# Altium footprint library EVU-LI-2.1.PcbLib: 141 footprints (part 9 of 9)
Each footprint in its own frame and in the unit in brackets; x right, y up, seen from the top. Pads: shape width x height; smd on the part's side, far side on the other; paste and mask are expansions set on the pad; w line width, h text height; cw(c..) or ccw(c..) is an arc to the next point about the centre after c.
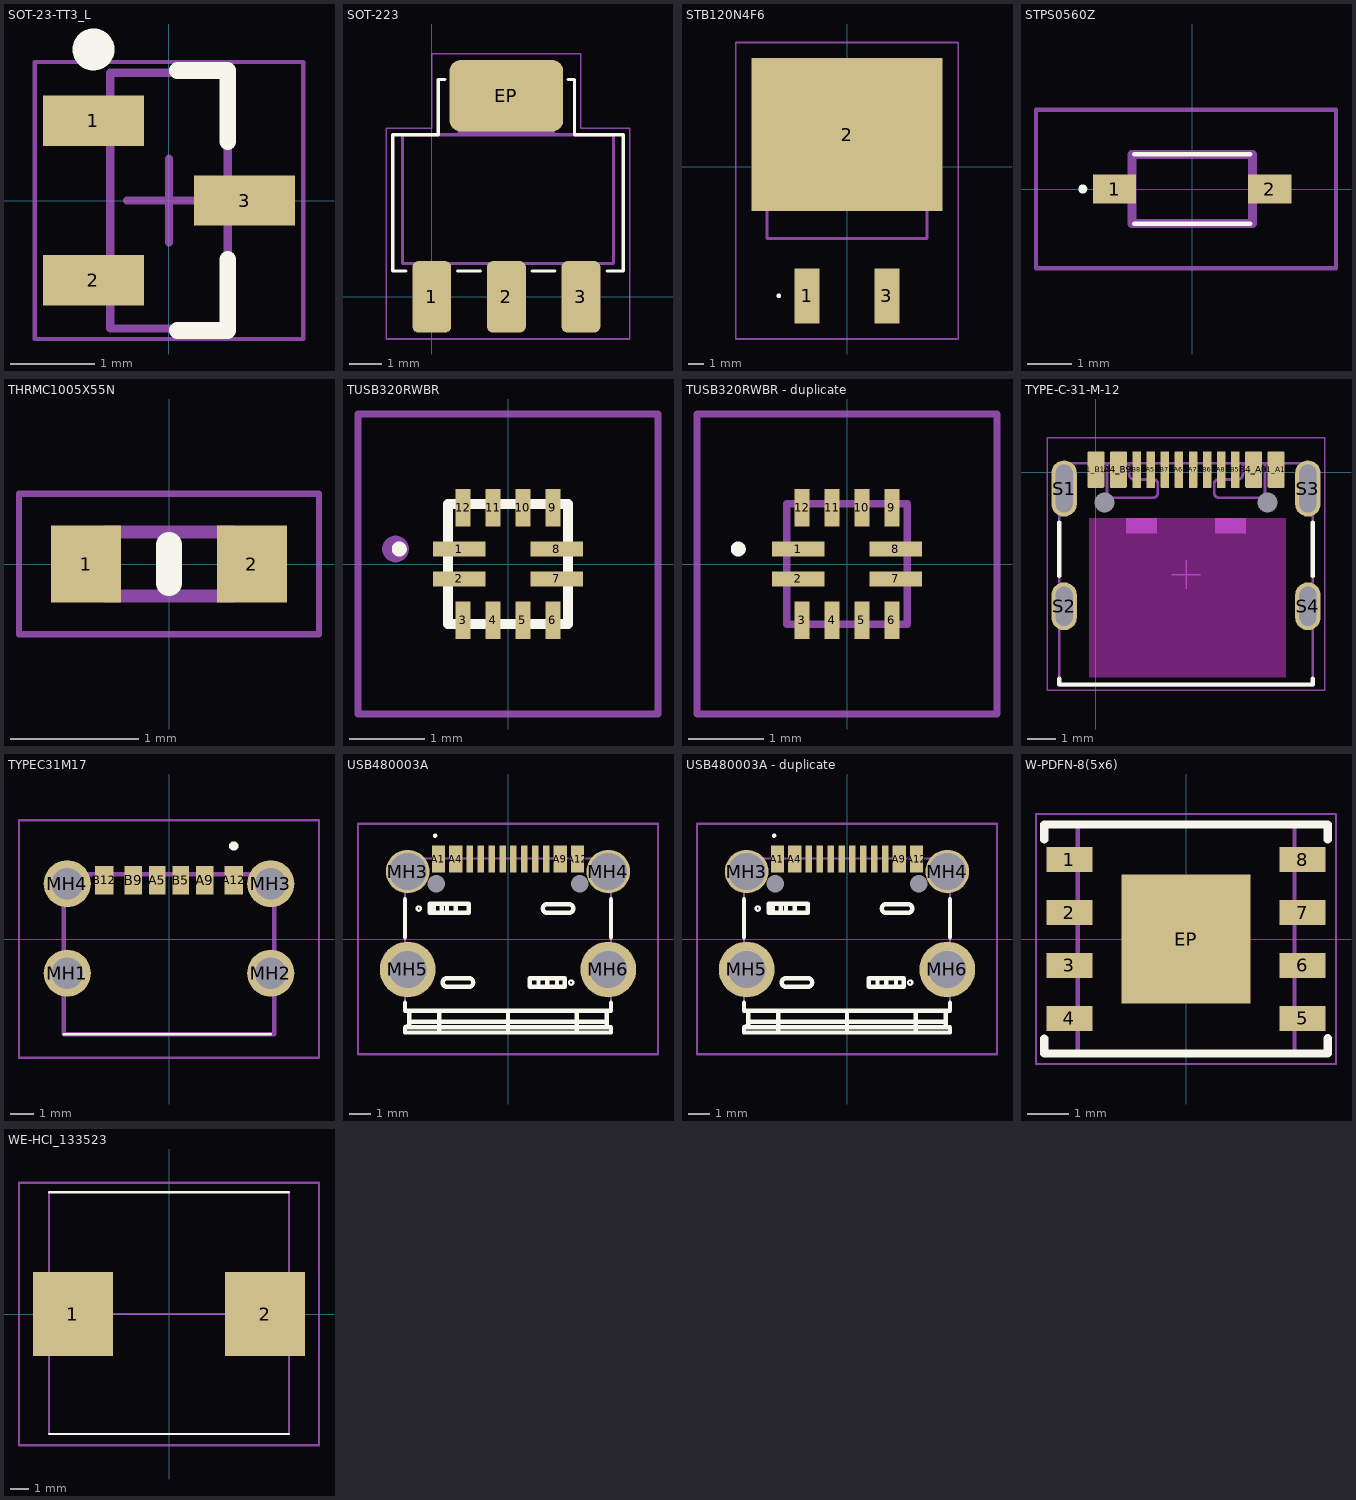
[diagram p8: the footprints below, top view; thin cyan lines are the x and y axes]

## SOT-23-TT3_L [mm] "SOT23, 3-Leads, Body 2.9x1.3mm, Pitch 0.95mm, Lead Span 2.4mm, IPC High Density"
height 1.12
pads (3):
  rect 1.2x0.6 smd: 1(-0.9,0.95) 2(-0.9,-0.95) 3(0.9,0)
Top Overlay:
  circle w0.25: c-0.9,1.8 r0.125
  lines w0.2: 0.1,-1.55 0.7,-1.55 0.7,-0.7 ; 0.1,1.55 0.7,1.55 0.7,0.7
Mechanical 13:
  lines w0.1: -0.7,-1.525 -0.7,1.525 0.7,1.525 0.7,-1.525 -0.7,-1.525
Top Courtyard:
  lines w0.05: -1.6,-1.65 -1.6,1.65 1.6,1.65 1.6,-1.65 -1.6,-1.65
  lines w0.1: -0.5,0 0.5,0 ; 0,-0.5 0,0.5
3D body: height 1.12, standoff 0.01, extent -0.7,-1.525 0.7,1.525

## SOT-223 [mm]
height 1.1
pads (4):
  rrect30% 1.2x2.2 smd mask+0.05: 1(0,0) 2(2.3,0) 3(4.6,0)
  rrect30% 3.5x2.2 smd mask+0.05: EP(2.3,6.2)
Top Overlay:
  lines w0.1: -0.8,0.8 -1.2,0.8 -1.2,5 0.2,5 0.2,6.7 0.4,6.7 ; 0.8,0.8 1.5,0.8 ; 3.1,0.8 3.8,0.8 ; 4.2,6.7 4.4,6.7 4.4,5 5.9,5 5.9,0.8 5.4,0.8
  text "." at -1.1,-0.3 h5
Top Assembly:
  rectangle: 4.2,-0.42 5,1
  rectangle: 1.9,-0.42 2.7,1
  region: 3.8,6.6 0.8,6.6 0.8,5 3.8,5
  rectangle: -0.4,-0.42 0.4,1
  lines w0.1: -0.9,1.03 -0.9,5 5.6,5 5.6,1.03 -0.9,1.03
  text ".Designator" at 0.604,3.246 h0.8
  text "." at -0.1,1.3 h3
Top Value:
  text ".Comment" at 1.251,2.771 h0.5
Top Courtyard:
  lines w0.05: -1.4,-1.3 6.1,-1.3 6.1,5.199 4.599,5.199 4.599,7.5 0.001,7.5 0.001,5.199 -1.4,5.199 -1.4,-1.3
3D body "SOT223-3.step": height 1.6, standoff 0, extent -0.9,-0.437 5.6,6.637

## STB120N4F6 [mm]
pads (3):
  rect 1.6x3.5 smd: 1(-2.54,-8.24) 3(2.54,-8.24)
  rect 12.2x9.75 smd: 2(0,2.035)
Top Overlay:
  lines w0.2: -4.4,-8.24 ccw(c-4.35,-8.24) -4.3,-8.24 ; -4.4,-8.24 cw(c-4.35,-8.24) -4.3,-8.24 ; -4.4,-8.24 ccw(c-4.35,-8.24) -4.3,-8.24
Mechanical 13:
  lines w0.2: -5.1,-4.575 -5.1,4.575 5.1,4.575 5.1,-4.575 -5.1,-4.575
Top Courtyard:
  lines w0.1: -7.1,-10.99 -7.1,7.91 7.1,7.91 7.1,-10.99 -7.1,-10.99
3D body "STB140NF75T4.stp": height 4.6, standoff -0.05, extent -5.194,-8.103 5.194,5.375

## STPS0560Z [mm]
pads (2):
  rect 0.97x0.65 smd: 1(-1.74,0) 2(1.74,0)
Top Overlay:
  lines w0.1: -1.3,-0.775 1.3,-0.775 ; -1.3,0.775 1.3,0.775 ; -2.5,0 ccw(c-2.45,0) -2.4,0 ccw(c-2.45,0) -2.5,0
Mechanical 13:
  lines w0.2: -1.35,-0.775 1.35,-0.775 1.35,0.775 -1.35,0.775 -1.35,-0.775
Top Courtyard:
  lines w0.1: -3.5,-1.775 3.225,-1.775 3.225,1.775 -3.5,1.775 -3.5,-1.775
3D body "STPS0560Z.stp": height 1.45, standoff 0, extent -1.975,-0.85 1.975,0.85

## THRMC1005X55N [mm]
pads (2):
  rect 0.55x0.6 smd: 1(-0.65,0) 2(0.65,0)
Top Overlay:
  lines w0.2: 0,-0.15 0,0.15
Mechanical 13:
  lines w0.1: -0.5,-0.25 0.5,-0.25 0.5,0.25 -0.5,0.25 -0.5,-0.25
Top Courtyard:
  lines w0.05: -1.175,-0.55 1.175,-0.55 1.175,0.55 -1.175,0.55 -1.175,-0.55
3D body "NTCG103JF103F.stp": height 0.55, standoff 0, extent -0.5,-0.25 0.5,0.25

## TUSB320RWBR [mm]
pads (12):
  rect 0.7x0.2 smd: 1(-0.65,0.2) 2(-0.65,-0.2) 7(0.65,-0.2) 8(0.65,0.2)
  rect 0.2x0.5 smd: 3(-0.6,-0.75) 4(-0.2,-0.75) 5(0.2,-0.75) 6(0.6,-0.75) 9(0.6,0.75) 10(0.2,0.75) 11(-0.2,0.75) 12(-0.6,0.75)
Top Overlay:
  lines w0.1: -1.5,0.2 cw(c-1.45,0.2) -1.4,0.2 cw(c-1.45,0.2) -1.5,0.2
  lines w0.127: -0.8,-0.8 0.8,-0.8 0.8,0.8 -0.8,0.8 -0.8,-0.8
Top Assembly:
  circle w0.254: c-1.5,0.2 r0.05
  lines w0.127: -0.8,-0.8 0.8,-0.8 0.8,0.8 -0.8,0.8 -0.8,-0.8
Mechanical 13:
  lines w0.1: -0.8,-0.8 0.8,-0.8 0.8,0.8 -0.8,0.8 -0.8,-0.8
Top Courtyard:
  lines w0.1: -2,-2 2,-2 2,2 -2,2 -2,-2
3D body "TUSB320RWBR.stp": height 0.5, standoff 0, extent -0.8,-0.8 0.8,0.8

## TUSB320RWBR - duplicate [mm]
pads (12):
  rect 0.7x0.2 smd: 1(-0.65,0.2) 2(-0.65,-0.2) 7(0.65,-0.2) 8(0.65,0.2)
  rect 0.2x0.5 smd: 3(-0.6,-0.75) 4(-0.2,-0.75) 5(0.2,-0.75) 6(0.6,-0.75) 9(0.6,0.75) 10(0.2,0.75) 11(-0.2,0.75) 12(-0.6,0.75)
Top Overlay:
  lines w0.1: -1.5,0.2 ccw(c-1.45,0.2) -1.4,0.2 ccw(c-1.45,0.2) -1.5,0.2
Mechanical 13:
  lines w0.1: -0.8,-0.8 -0.8,0.8 0.8,0.8 0.8,-0.8 -0.8,-0.8
Top Courtyard:
  lines w0.1: -2,-2 -2,2 2,2 2,-2 -2,-2
3D body "TUSB320RWBR.stp": height 0.5, standoff 0, extent -0.8,-0.8 0.8,0.8

## TYPE-C-31-M-12 [mm] "USB TYPE-C 5A 16P Female SMD USB Connectors"
height 3.24
pads (18):
  rrect15% 0.6x1.3 smd mask+0.05: A1_B12(0,0.1) A4_B9(0.8,0.1) B1_A12(6.4,0.1) B4_A9(5.6,0.1)
  rrect15% 0.3x1.3 smd mask+0.05: A5(1.95,0.1) A6(2.95,0.1) A7(3.45,0.1) A8(4.45,0.1) B5(4.95,0.1) B6(3.95,0.1) B7(2.45,0.1) B8(1.45,0.1)
  oval 0.9x2 hole 0.6 slot 1.7 at 90 deg mask+0.05: S1(-1.125,-0.57) S3(7.525,-0.57)
  oval 0.9x1.7 hole 0.6 slot 1.4 at 90 deg mask+0.05: S2(-1.125,-4.75) S4(7.525,-4.75)
  round 0 hole 0.7 unplated: ""(0.31,-1.07) ""(6.09,-1.07)
Top Layer keep-out:
  rectangle: -0.25,-7.275 6.75,-1.625
Top Overlay:
  lines w0.15: -1.3,-7.32 -1.3,-7.53 7.7,-7.53 7.7,-7.32 ; -1.3,-3.675 -1.3,-1.775 ; 7.7,-3.675 7.7,-1.775
Top Assembly:
  region: 5.325,-1.625 4.225,-1.625 4.225,-2.175 5.325,-2.175
  region: -1.3,-4.18 -1.3,-5.28 -0.875,-5.28 -0.875,-4.18
  region: 7.275,-4.194 7.275,-5.294 7.7,-5.294 7.7,-4.194
  region: 7.275,-0.022 7.275,-1.122 7.7,-1.122 7.7,-0.022
  region: -1.3,-0.024 -1.3,-1.124 -0.875,-1.124 -0.875,-0.024
  rectangle: 1.075,-2.175 2.175,-1.625
  rectangle: 4.822,0.325 5.065,0.65
  rectangle: 4.321,0.325 4.564,0.65
  rectangle: 3.828,0.325 4.071,0.65
  rectangle: 3.325,0.325 3.568,0.65
  rectangle: 2.834,0.325 3.077,0.65
  rectangle: 2.341,0.325 2.584,0.65
  rectangle: 1.825,0.325 2.068,0.65
  rectangle: 1.325,0.325 1.567,0.65
  rectangle: -0.238,0.325 0.235,0.65
  rectangle: 0.556,0.325 1.029,0.65
  rectangle: 5.365,0.325 5.838,0.65
  rectangle: 6.2,0.325 6.673,0.65
  lines w0.1: 0.4,0.3 0.4,-0.701 ccw(c0.599,-0.701) 0.599,-0.9 ; 1.182,0.325 1.182,-0.057 ccw(c1.375,-0.057) 1.375,-0.25 ; 5.218,0.325 5.218,-0.057 cw(c5.025,-0.057) 5.025,-0.25 ; 6,0.3 6,-0.701 cw(c5.801,-0.701) 5.801,-0.9 ; 0.599,-0.9 2.025,-0.9 ; 0.599,-0.9 2.025,-0.9 ; 1.375,-0.25 2.05,-0.25 ; 1.375,-0.25 1.475,-0.25 2.05,-0.25 ; 2.025,-0.9 ccw(c2.025,-0.725) 2.2,-0.725 ; 2.05,-0.25 cw(c2.05,-0.4) 2.2,-0.4 ; 2.2,-0.725 2.2,-0.4 ; 2.2,-0.725 2.2,-0.4 ; 4.2,-0.725 ccw(c4.375,-0.725) 4.375,-0.9 ; 4.2,-0.725 4.2,-0.4 ; 4.2,-0.725 4.2,-0.4 ; 4.2,-0.4 cw(c4.35,-0.4) 4.35,-0.25 ; 4.35,-0.25 5.025,-0.25 ; 4.35,-0.25 4.925,-0.25 5.025,-0.25 ; 4.375,-0.9 5.801,-0.9 ; 4.375,-0.9 5.801,-0.9 ; -1.3,-7.575 7.7,-7.575 7.7,0.325 -1.3,0.325 -1.3,-7.575
  text ".Designator" at -0.55,-3.65 h2
Top Value:
  text ".Comment" at -0.602,-4.403 h1.5
Top Courtyard:
  lines w0.05: 2.7,-3.625 3.7,-3.625 ; 3.2,-4.125 3.2,-3.125 ; -1.725,-7.725 8.125,-7.725 8.125,1.225 -1.725,1.225 -1.725,-7.725
3D body "HRO_TYPE-C-31-M-12.step": height 3.16, standoff -1.04, extent -1.275,-7.35 7.675,0.55

## TYPEC31M17 [mm]
pads (10):
  rect 0.7x1.2 smd: A5(-0.5,2.5) B5(0.5,2.5)
  rect 0.76x1.2 smd: A9(1.52,2.5) B9(-1.52,2.5)
  rect 0.8x1.2 smd: A12(2.75,2.5) B12(-2.75,2.5)
  round 2 hole 1.346: MH1(-4.32,-1.45) MH2(4.32,-1.45) MH3(4.32,2.35) MH4(-4.32,2.35)
Top Overlay:
  lines w0.1: -4.47,-4.05 4.32,-4.05
  lines w0.2: 2.75,3.85 cw(c2.75,3.95) 2.75,4.05 cw(c2.75,3.95) 2.75,3.85
Mechanical 13:
  lines w0.2: -4.47,-4.05 -4.47,2.75 4.47,2.75 4.47,-4.05 -4.47,-4.05
Top Courtyard:
  lines w0.1: -6.37,-5.05 -6.37,5.05 6.37,5.05 6.37,-5.05 -6.37,-5.05
3D body "TYPE-C-31-M-17.stp": height 3.26, standoff -0.94, extent -4.47,-4.31 4.48,3.09

## USB480003A [mm]
pads (18):
  rect 0.6x1.25 smd: A1(-3.2,3.675) A4(-2.4,3.675) A9(2.4,3.675) A12(3.2,3.675)
  rect 0.3x1.25 smd: A5(-1.25,3.675) A6(-0.25,3.675) A7(0.25,3.675) A8(1.25,3.675) B5(1.75,3.675) B6(0.75,3.675) B7(-0.75,3.675) B8(-1.75,3.675)
  round 0.4 hole 0.8 unplated: MH1(-3.3,2.54) MH2(3.3,2.54)
  round 2 hole 1.71: MH3(-4.61,3.1) MH4(4.61,3.1)
  round 2.565 hole 1.71: MH5(-4.61,-1.4) MH6(4.61,-1.4)
Top Overlay:
  lines w0.1: -4.2,1.4 cw(c-4.1,1.4) -4,1.4 cw(c-4.1,1.4) -4.2,1.4 ; -3.35,4.7 ccw(c-3.35,4.75) -3.35,4.8 ccw(c-3.35,4.75) -3.35,4.7 ; 2.8,-2 ccw(c2.9,-2) 3,-2 ccw(c2.9,-2) 2.8,-2
  lines w0.2: -4.735,-4.05 ccw(c-4.735,-3.832) -4.539,-3.925 ; -4.735,-2.925 -4.735,-3.3 4.735,-3.3 4.735,-2.925 ; -4.735,0.075 -4.735,1.825 ; -4.538,-3.925 -4.538,-3.3 ; -4.538,-3.8 4.538,-3.8 ; -3.6,1.613 -1.8,1.613 -1.8,1.2 -3.6,1.2 -3.6,1.6 -3.4,1.6 -3.4,1.2 ; -3.157,-4.3 -3.157,-3.3 ; -3.05,1.2 -3.05,1.613 ; -2.8,1.2 -2.8,1.6 ; -2.4,1.2 -2.4,1.6 ; 0,-4.3 0,-3.3 ; 1.4,-2.2 1.4,-1.8 ; 1.8,-2.2 1.8,-1.8 ; 2.25,-2.2 2.25,-1.8 ; 3.157,-4.3 3.157,-3.3 ; 4.538,-3.3 4.538,-3.925 ccw(c4.676,-3.925) 4.735,-4.05 ; 4.735,0.075 4.735,1.825 ; 4.735,-4.05 -0.986,-4.05 -4.735,-4.05 -4.735,-4.3 4.735,-4.3 4.735,-4.05 ; -2.8,-2.2 cw(c-2.8,-2) -2.8,-1.8 -1.8,-1.8 cw(c-1.8,-2) -1.8,-2.2 -2.8,-2.2 ; 1,-2.2 1,-1.8 2.6,-1.8 2.6,-2.2 2.4,-2.2 1,-2.2 ; 1.8,1.2 cw(c1.8,1.4) 1.8,1.6 2.8,1.6 cw(c2.8,1.4) 2.8,1.2 1.8,1.2
Mechanical 13:
  lines w0.1: -4.735,-4.05 ccw(c-4.735,-3.832) -4.539,-3.925 ; -4.538,-4.3 -4.735,-4.3 ; -4.538,-3.925 -4.538,-3.3 ; -4.538,-3.8 4.538,-3.8 ; -4.735,-4.3 -4.735,-4.05 4.735,-4.05 4.735,-4.3 -4.735,-4.3 ; -4.735,-3.3 -4.735,3.7 4.735,3.7 4.735,-3.3 -4.735,-3.3
Top Courtyard:
  lines w0.1: -6.893,-5.3 -6.893,5.3 6.893,5.3 6.893,-5.3 -6.893,-5.3
3D body "USB4800-03-A.stp": height 5.39, standoff -1.29, extent -4.745,-4.21 4.725,4.19

## USB480003A - duplicate [mm]
pads (18):
  rect 0.6x1.25 smd: A1(-3.2,3.675) A4(-2.4,3.675) A9(2.4,3.675) A12(3.2,3.675)
  rect 0.3x1.25 smd: A5(-1.25,3.675) A6(-0.25,3.675) A7(0.25,3.675) A8(1.25,3.675) B5(1.75,3.675) B6(0.75,3.675) B7(-0.75,3.675) B8(-1.75,3.675)
  round 0.4 hole 0.8 unplated: MH1(-3.3,2.54) MH2(3.3,2.54)
  round 2 hole 1.71: MH3(-4.61,3.1) MH4(4.61,3.1)
  round 2.565 hole 1.71: MH5(-4.61,-1.4) MH6(4.61,-1.4)
Top Overlay:
  lines w0.1: -4.2,1.4 ccw(c-4.1,1.4) -4,1.4 ccw(c-4.1,1.4) -4.2,1.4 ; -3.35,4.7 cw(c-3.35,4.75) -3.35,4.8 cw(c-3.35,4.75) -3.35,4.7 ; 2.8,-2 cw(c2.9,-2) 3,-2 cw(c2.9,-2) 2.8,-2
  lines w0.2: -4.735,-4.05 ccw(c-4.735,-3.832) -4.539,-3.925 ; -4.735,-2.925 -4.735,-3.3 4.735,-3.3 4.735,-2.925 ; -4.735,0.075 -4.735,1.825 ; -4.538,-3.925 -4.538,-3.3 ; -4.538,-3.8 4.538,-3.8 ; -3.6,1.613 -1.8,1.613 -1.8,1.2 -3.6,1.2 -3.6,1.6 -3.4,1.6 -3.4,1.2 ; -3.157,-4.3 -3.157,-3.3 ; -3.05,1.2 -3.05,1.613 ; -2.8,1.2 -2.8,1.6 ; -2.4,1.2 -2.4,1.6 ; 0,-4.3 0,-3.3 ; 1.4,-2.2 1.4,-1.8 ; 1.8,-2.2 1.8,-1.8 ; 2.25,-2.2 2.25,-1.8 ; 3.157,-4.3 3.157,-3.3 ; 4.538,-3.3 4.538,-3.925 ccw(c4.676,-3.925) 4.735,-4.05 ; 4.735,0.075 4.735,1.825 ; 4.735,-4.05 4.735,-4.3 -4.735,-4.3 -4.735,-4.05 -0.986,-4.05 4.735,-4.05 ; -2.8,-2.2 cw(c-2.8,-2) -2.8,-1.8 -1.8,-1.8 cw(c-1.8,-2) -1.8,-2.2 -2.8,-2.2 ; 1,-2.2 2.4,-2.2 2.6,-2.2 2.6,-1.8 1,-1.8 1,-2.2 ; 1.8,1.2 cw(c1.8,1.4) 1.8,1.6 2.8,1.6 cw(c2.8,1.4) 2.8,1.2 1.8,1.2
Mechanical 13:
  lines w0.1: -4.735,-4.05 ccw(c-4.735,-3.832) -4.539,-3.925 ; -4.538,-4.3 -4.735,-4.3 ; -4.538,-3.925 -4.538,-3.3 ; -4.538,-3.8 4.538,-3.8 ; -4.735,-4.3 4.735,-4.3 4.735,-4.05 -4.735,-4.05 -4.735,-4.3 ; -4.735,-3.3 4.735,-3.3 4.735,3.7 -4.735,3.7 -4.735,-3.3
Top Courtyard:
  lines w0.1: -6.893,-5.3 6.893,-5.3 6.893,5.3 -6.893,5.3 -6.893,-5.3
3D body "USB4800-03-A.stp": height 5.39, standoff -1.29, extent -4.745,-4.21 4.725,4.19

## W-PDFN-8(5x6) [mm]
pads (9):
  rect 1.1x0.6 smd mask+0.05: 1(-2.8,1.905) 2(-2.8,0.635) 3(-2.8,-0.635) 4(-2.8,-1.905) 5(2.8,-1.905) 6(2.8,-0.635) 7(2.8,0.635) 8(2.8,1.905)
  rect 3.1x3.1 smd mask+0.05: EP(0,0)
Top Overlay:
  lines w0.2: -3.4,-2.387 -3.4,-2.75 ; -3.4,2.386 -3.4,2.75 3.4,2.75 3.4,2.389 ; 3.4,-2.384 3.4,-2.75 ; -3.4,-2.75 -3.182,-2.75 3.194,-2.75 3.4,-2.75 ; -3.4,-2.75 -3.4,-2.75 ; 3.4,-2.75 3.4,-2.75
  text "." at -3.182,3.15 h6
Top Assembly:
  lines w0.1: -2.6,-2.75 -2.6,2.75 2.6,2.75 2.6,-2.75 -2.6,-2.75
  text ".Designator" at -2.092,0.089 h1
  text "." at -2.263,1.918 h6
Top Value:
  text ".comment" at -1.66,-0.983 h1
Top Courtyard:
  lines w0.05: -0.35,0 0.35,0 ; 0,-0.35 0,0.35 ; -3.6,-3 -3.6,3 3.6,3 3.6,-3 -3.6,-3
3D body "User Library-DFN8-5X6.STEP": height 0.95, standoff 0, extent -3.057,-2.511 3.043,2.489

## WE-HCI_133523 [mm]
pads (2):
  rect 4.25x4.5 smd: 1(-5.12,0) 2(5.12,0)
Top Overlay:
  lines w0.127: -6.4,-6.4 6.4,-6.4 ; -6.4,6.5 6.4,6.5
Mechanical 13:
  lines w0.127: -6.4,-6.35 -6.4,6.45 ; -5,0 5,0 ; 6.4,-6.4 6.4,6.5
Top Courtyard:
  lines w0.127: -8,-7 -8,7 8,7 8,-7 -8,-7
3D body "744314850.stp": height 4.85, standoff -0.15, extent -3.5,-3.45 3.5,3.45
